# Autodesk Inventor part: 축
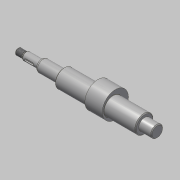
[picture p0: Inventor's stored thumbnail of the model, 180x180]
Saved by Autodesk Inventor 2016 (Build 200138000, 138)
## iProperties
Created: 2015-12
Part Number: 축
Document SubType Name: Modeling
Designer: mdu
Density: 7.86 g/cm^3
Material: 강철, 연강
Appearance: 강철
Author: mdu
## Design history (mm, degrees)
sketch "스케치1"
  geometry: L1 (62, 100.9)-(62, 67.1) reference; L2 (51, 101.2)-(51, 84) reference; L3 (-51, 84)-(-51, 101.2) reference; L4 (-62, 67.1)-(-62, 100.9) reference; L5 (-51.6, 91.5)-(-61.4, 91.5) reference; L6 (51.6, 91.5)-(61.4, 91.5) reference; L7 (67, 84)-(-109, 84); L8 (-77, 64.201)-(-77, 103.799) reference; L9 (67, 84)-(67, 91.5); L10 (67, 91.5)-(51, 91.5); L11 (51, 91.5)-(51, 95.5); L12 (51, 95.5)-(-51, 95.5); L13 (-51, 95.5)-(-51, 91.5); L14 (-51, 91.5)-(-79, 91.5); L15 (-79, 91.5)-(-79, 89); L16 (-79, 89)-(-99, 89); L17 (-99, 89)-(-99, 87); L18 (-100.5, 88)-(-109, 88); L19 (-109, 88)-(-109, 84); L20 (-99, 87)-(-100.5, 87); L21 (-100.5, 87)-(-100.5, 88); 2 further points
  constraints: 32 end point, 7 parallel, 6 point on line, 5 perpendicular, 2 collinear, 2 horizontal, 1 midpoint, 4 other
  dimensions: "d0" = 5 distance from line of L7.start L1; "d2" = 2 distance between parallel lines of L15 L8; "d3" = 23 diameter of L12 L7; "d4" = 10 diameter of L16 L7; "d5" = 1.5 distance of L17.end L20.end; "d6" = 6 diameter of L20 L7; "d7" = 20 distance of L15.end L16.end; "d8" = 10 distance between parallel lines of L17 L19; "d9" = 8 diameter of L18 L7
revolve "회전1" sketch "스케치1" stored, may be unused: angle "d10" = 90 deg
sketch "스케치2"
  geometry: C1 r 11.5 at (84, 0) reference; C2 r 11.5 at (84, 0) reference; C3 r 16.5 at (87, 0); 1 further point
  constraints: 1 centre point, 1 horizontal alignment
  dimensions: "d11" = 33 diameter of C3; "d12" = 3 distance of C3.centre C1.centre
extrude "돌출1" join sketch "스케치2" stored distance "d13" = 22; taper "d14" = 0 deg
chamfer "모따기1" distance "d15" = 1; stored, may be unused: second distance "d16" = 2, angle "d17" = 45 deg
feature "스레드1" dims "d18" = 10, "d19" = 0
node "작업 평면1"
sketch "스케치3"
  geometry: L1 (-5.5, -1.5)-(3.5, -1.5); L2 (3.5, 1.5)-(-5.5, 1.5); L3 (-10, -4)-(-10, 4) reference; A1 r 1.5 centre (3.5, 0) between (3.5, -1.5) and (3.5, 1.5); A2 r 1.5 centre (-5.5, 0) between (-5.5, 1.5) and (-5.5, -1.5); 2 further points
  constraints: 4 end point, 4 point on circle, 4 tangent, 2 centre point, 1 horizontal, 1 horizontal alignment, 1 midpoint, 1 parallel
  dimensions: "d20" = 3 distance between parallel lines of L1 L2; "d21" = 12 dimension on A1 A2; "d22" = 3 distance edge to line of A2 L3
extrude "돌출2" cut sketch "스케치3" distance "d23" = 1.8; taper "d24" = 0 deg
fillet "모깎기1" dims "d25" = 0.3
fillet "모깎기2" dims "d26" = 3
node "솔리드1"
node "참조1"
node "참조2"
node "참조3"
node "참조4"
node "참조5"
node "투영된 루프1"
